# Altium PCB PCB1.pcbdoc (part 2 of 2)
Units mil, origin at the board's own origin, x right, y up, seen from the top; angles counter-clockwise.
Board outline 2817.44 x 1578.14 mil, 2 copper layers (Top Layer, Bottom Layer); 132 components, 113 nets, 538 pads, 285 vias.
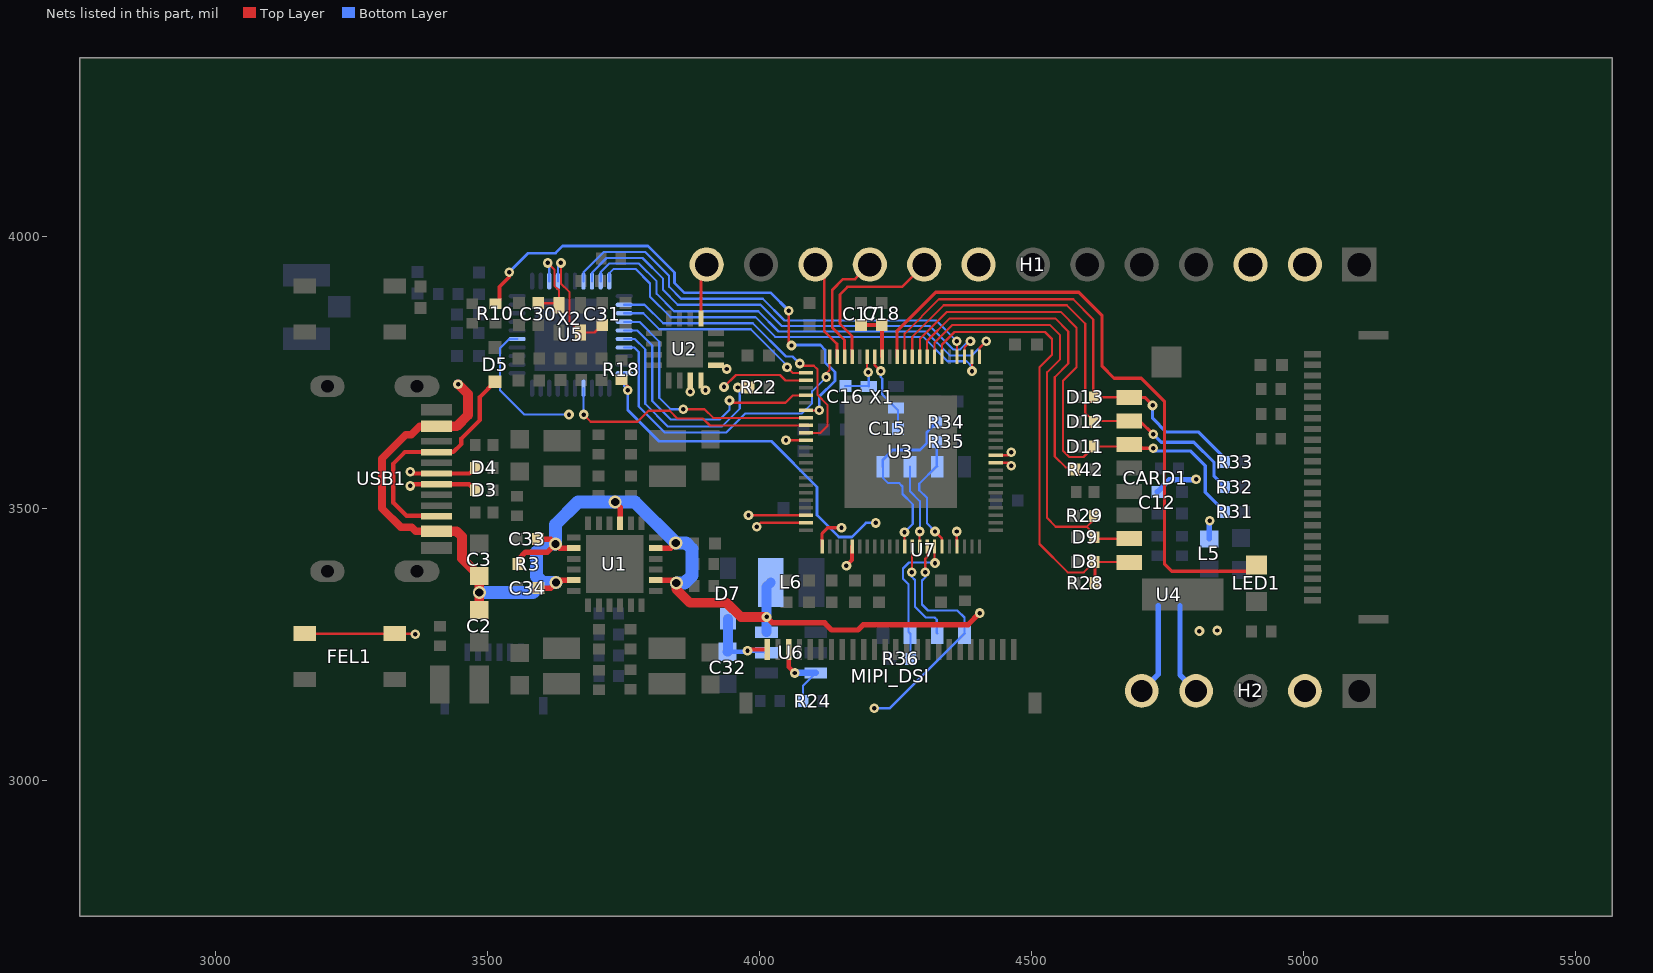
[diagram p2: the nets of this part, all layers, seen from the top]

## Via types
v1: diameter 18, hole 8, Top Layer to Bottom Layer, 271 vias
v2: diameter 24, hole 15, Top Layer to Bottom Layer, 14 vias

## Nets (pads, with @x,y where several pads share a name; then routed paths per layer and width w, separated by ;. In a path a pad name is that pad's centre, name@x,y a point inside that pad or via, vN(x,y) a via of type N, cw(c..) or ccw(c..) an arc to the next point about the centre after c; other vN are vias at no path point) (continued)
HX1: C30.1 U5.3 X2.1 | length 160.9
  Top Layer w4: C30.1@3592.85,3876.99 3626.85,3876.99 X2.1@3630.85,3872.99 3630.85,3900.78 3622.5,3909.13 3622.5,3939.13 v1(3610.5,3951.13)
  Bottom Layer w4: v1(3610.5,3951.13) 3613.13,3948.5 U5.3@3613.13,3917.53
HX2: C31.1 U5.4 X2.3 | length 224.6
  Top Layer w4: v1(3634.5,3951.13) 3634.5,3913.13 3650.5,3897.13 3650.5,3843.34 X2.3@3670.85,3822.99 3696.35,3822.99 C31.1@3710.5,3837.14
  Bottom Layer w4: U5.4@3628.88,3917.53 3628.88,3945.51 v1(3634.5,3951.13)
HXIN: C16.1 U3.16 X1.1 | length 99.2
  Top Layer w4: U3.16@4197.49,3778.64 4197.49,3752.14 v1(4199.5,3750.13)
  Bottom Layer w4: C16.1@4157.5,3725.05 4199.5,3725.05 X1.1@4200.5,3724.05 4200.5,3749.14 v1(4199.5,3750.13)
HXOUT: C15.1 U3.15 X1.3 | length 150.5
  Top Layer w4: U3.15@4211.27,3778.64 4211.27,3763.36 v1(4222.5,3752.13)
  Bottom Layer w4: v1(4222.5,3752.13) 4222.5,3741.13 4225.5,3738.13 4225.5,3709.05 X1.3@4250.5,3684.05 4254.49,3680.06 C15.1@4254.49,3646.05
LED: LED1.2 U3.12 | length 1184.7
  Top Layer w6: U3.12@4252.61,3778.64 4252.61,3826.24 4323.5,3897.13 4586.5,3897.13 4629.5,3854.13 4629.5,3761.13 4651.5,3739.13 4701.5,3739.13 4744.5,3696.13 4744.5,3397.13 4757.5,3384.13 4902.04,3384.13 LED1.2@4913.5,3395.6
LEDA: C32.2 D7.1 MIPI_DSI.24 U6.5 | length 172.8
  Top Layer w8: v1(3977.5,3238.13) 3979.7,3240.33 MIPI_DSI.24@4014.1,3240.33
  Bottom Layer w8: C32.2@3940.92,3236.06 3975.43,3236.06 v1(3977.5,3238.13) 4009.12,3238.13 U6.5@4012.72,3234.54
  Bottom Layer w18: C32.2@3940.92,3236.06 3941.5,3236.64 D7.1@3941.5,3296.93
LEDK: MIPI_DSI.22 R24.2 U6.3 | length 147.6
  Top Layer w8: MIPI_DSI.22@4053.5,3240.33 4053.5,3208.13 v1(4064.5,3197.13)
  Bottom Layer w4: R24.2@4079.92,3145.54 4079.92,3173.94 U6.3@4103.12,3197.14
  Bottom Layer w12: v1(4064.5,3197.13) U6.3@4103.12,3197.14
LINEOUTP: C12.1 U3.49 | length 1142.3
  Top Layer w7: v1(4159.5,3394.13) 4169.93,3404.56 U3.49@4169.93,3429.62
  Mid-Layer 1 w7: v1(4159.5,3394.13) 4302.5,3251.13 4456.5,3251.13 4491.5,3286.13 4796.5,3286.13 v1(4808.5,3274.13)
  Mid-Layer 2 w7: v1(4802.5,3553.13) 4807.5,3548.13 4807.5,3467.13 4823.5,3451.13 4823.5,3289.13 v1(4808.5,3274.13)
  Bottom Layer w10: C12.1@4731.05,3530.3 4752.88,3552.13 4798.5,3552.13 4799.5,3553.13 v1(4802.5,3553.13)
LPCLK: R18.1 U3.63 U5.20 | length 871.8
  Top Layer w4: R18.1@3745.67,3736.24 3757.5,3724.41 v1(3757.5,3717.13)
  Top Layer w5: v1(4362.5,3457.13) 4362.5,3429.97 U3.63@4362.85,3429.62
  Mid-Layer 1 w5: v1(4213.5,3473.13) 4346.5,3473.13 v1(4362.5,3457.13)
  Bottom Layer w4: U5.20@3750.9,3748.26 3750.9,3723.73 v1(3757.5,3717.13)
  Bottom Layer w5: v1(3757.5,3717.13) 3757.5,3680.13 3814.5,3623.13 4021.5,3623.13 4105.5,3539.13 4105.5,3487.21 4145.58,3447.13 4169.5,3447.13 4195.5,3473.13 v1(4213.5,3473.13)
PE10: H1.8 U3.32 | length 573
  Top Layer w5: v1(4048.5,3625.13) 4048.83,3624.8 U3.32@4084.99,3624.8
  Mid-Layer 2 w4: v1(4048.5,3625.13) 4087.5,3664.13 4087.5,3747.13 4144.5,3804.13 4187.5,3804.13 4289.5,3906.13 4360.5,3906.13 H1.8@4402.5,3948.13
PE11: H1.11 U3.20 | length 186
  Top Layer w5: H1.11@4102.5,3948.13 4118.5,3932.13 4118.5,3826.13 4142.37,3802.26 U3.20@4142.37,3778.64
PE12: H1.10 U3.19 | length 220.3
  Top Layer w5: U3.19@4156.15,3778.64 4156.15,3809.48 4133.5,3832.13 4133.5,3901.13 4153.5,3921.13 4175.5,3921.13 H1.10@4202.5,3948.13
PE13: H1.9 U3.18 | length 301.6
  Top Layer w5: U3.18@4169.93,3778.64 4169.93,3816.7 4147.5,3839.13 4147.5,3893.13 4161.5,3907.13 4261.5,3907.13 H1.9@4302.5,3948.13
PH0: H2.2 U3.45 | length 1113.8
  Top Layer w6: U3.45@4114.81,3429.62 4114.81,3453.68 4125.26,3464.13 v1(4150.5,3464.13)
  Mid-Layer 1 w6: v1(4150.5,3464.13) 4132.5,3446.13 4132.5,3398.13 4295.5,3235.13 4947.5,3235.13 5002.5,3180.13 H2.2@5002.5,3164.13
SDC0_CLK: R42.1 U3.8 | length 604
  Top Layer w4: U3.8@4307.73,3778.64 4307.73,3807.36 4349.5,3849.13 4543.5,3849.13 4567.5,3825.13 4567.5,3766.13 4542.5,3741.13 4542.5,3595.13 4562.5,3575.13 4576.51,3575.13 R42.1@4580.5,3571.14
SDC0_CMD: CARD1.3 D11.1 R31.1 U3.9 | length 982.1
  Top Layer w4: U3.9@4293.95,3778.64 4294.5,3779.19 4294.5,3811.13 4344.5,3861.13 4553.5,3861.13 4582.5,3832.13 4582.5,3759.13 4557.5,3734.13 4557.5,3606.13 4569.5,3594.13 4595.5,3594.13 4614.83,3613.47 D11.1@4615.24,3613.47 4675.63,3613.47 CARD1.3@4679.3,3617.13
  Top Layer w6: CARD1.3@4679.3,3617.13 4696.5,3617.13 4703.5,3610.13 v1(4723.5,3610.13)
  Bottom Layer w6: v1(4723.5,3610.13) 4728.5,3605.13 4792.5,3605.13 4819.5,3578.13 4819.5,3529.15 R31.1@4855.34,3493.31
SDC0_D0: CARD1.7 D9.1 R29.1 U3.7 | length 819.7
  Top Layer w4: U3.7@4321.51,3778.64 4321.51,3804.14 4354.5,3837.13 4533.5,3837.13 4552.5,3818.13 4552.5,3774.13 4528.5,3750.13 4528.5,3482.13 4544.5,3466.13 4601.5,3466.13 ; R29.1@4615.5,3486.13 4615.5,3480.13 4601.5,3466.13 ; CARD1.7@4679.3,3443.93 4618.04,3443.93 D9.1@4615.24,3446.73 4615.24,3452.39 4601.5,3466.13
SDC0_D1: CARD1.8 D8.1 R28.1 U3.6 | length 863.2
  Top Layer w4: U3.6@4335.29,3778.64 4335.29,3801.14 4358.29,3824.13 4524.5,3824.13 4537.5,3811.13 4537.5,3782.13 4514.5,3759.13 4514.5,3434.13 4566.5,3382.13 4596.02,3382.13 4613.78,3399.9 D8.1@4615.24,3401.36 ; D8.1@4611.72,3401.36 D8.1@4615.24,3401.36 ; CARD1.8@4679.3,3400.63 4678.58,3401.36 D8.1@4615.24,3401.36
  Top Layer w6: D8.1@4613.78,3399.9 4616.5,3397.18 R28.1@4616.5,3362.13
SDC0_D2: CARD1.1 D13.1 R33.1 U3.11 | length 882.7
  Top Layer w4: U3.11@4266.39,3778.64 4266.5,3778.75 4266.5,3821.13 4329.5,3884.13 4576.5,3884.13 4613.5,3847.13 4613.5,3705.95 D13.1@4615.24,3704.21 4678.83,3704.21 CARD1.1@4679.3,3703.73
  Top Layer w6: CARD1.1@4679.3,3703.73 4707.9,3703.73 v1(4722.5,3689.13)
  Bottom Layer w6: v1(4722.5,3689.13) 4722.5,3665.13 4747.5,3640.13 4807.5,3640.13 4855.34,3592.29 R33.1@4855.34,3584.68
SDC0_D3: CARD1.2 D12.1 R32.1 U3.10 | length 885.8
  Top Layer w4: U3.10@4280.17,3778.64 4280.5,3778.97 4280.5,3815.13 4338.5,3873.13 4564.5,3873.13 4598.5,3839.13 4598.5,3675.58 D12.1@4615.24,3658.84 4616.84,3660.43 CARD1.2@4679.3,3660.43
  Top Layer w6: CARD1.2@4679.3,3660.43 4699.2,3660.43 v1(4723.5,3636.13)
  Bottom Layer w6: v1(4723.5,3636.13) 4738.5,3621.13 4798.5,3621.13 4835.5,3584.13 4835.5,3558.83 R32.1@4855.34,3538.99
SDC1_CLK: R22.1 U5.16 | length 413.2
  Top Layer w4: v1(3959.5,3722.13) R22.1@3980.5,3722.14
  Bottom Layer w4: U5.16@3750.9,3811.26 3770.37,3811.26 3789.5,3792.13 3789.5,3692.13 3831.5,3650.13 3930.5,3650.13 3963.5,3683.13 3963.5,3718.13 v1(3959.5,3722.13)
SDC1_CMD: U3.31 U5.12 | length 561.1
  Top Layer w4: v1(4073.5,3766.13) 4077.5,3762.13 4099.5,3762.13 4106.5,3755.13 4106.5,3708.13 4124.5,3690.13 4124.5,3651.13 4111.95,3638.58 U3.31@4084.99,3638.58
  Bottom Layer w4: U5.12@3750.9,3874.25 3788.38,3874.25 3822.5,3840.13 3987.5,3840.13 4048.5,3779.13 4060.5,3779.13 v1(4073.5,3766.13)
SDC1_D0: U3.23 U5.13 | length 381.3
  Top Layer w4: v1(4050.5,3759.13) 4060.81,3748.82 U3.23@4084.99,3748.82
  Bottom Layer w4: U5.13@3750.9,3858.5 3786.13,3858.5 3815.5,3829.13 3983.5,3829.13 4050.5,3762.13 v1(4050.5,3759.13)
SDC1_D1: U3.29 U5.14 | length 467.6
  Top Layer w4: v1(3859.5,3682.13) 3898.5,3682.13 3914.49,3666.14 U3.29@4084.99,3666.14
  Bottom Layer w4: U5.14@3750.9,3842.75 3778.88,3842.75 3815.5,3806.13 3815.5,3703.13 3836.5,3682.13 v1(3859.5,3682.13)
SDC1_D2: U3.21 U5.17 | length 590.1
  Top Layer w4: v1(4122.5,3741.13) 4122.5,3748.13 4128.59,3754.22 U3.21@4128.59,3778.64
  Bottom Layer w4: U5.17@3750.9,3795.51 3769.12,3795.51 3777.5,3787.13 3777.5,3687.13 3825.5,3639.13 3938.5,3639.13 3973.5,3674.13 4077.5,3674.13 4096.5,3693.13 4096.5,3715.13 v1(4122.5,3741.13)
SDC1_D3: U3.26 U5.15 | length 493.4
  Top Layer w4: v1(3944.5,3698.13) 3948.5,3694.13 4047.5,3694.13 4060.85,3707.48 U3.26@4084.99,3707.48
  Bottom Layer w4: U5.15@3750.9,3827 3774.63,3827 3802.5,3799.13 3802.5,3697.13 3836.5,3663.13 3926.5,3663.13 3944.5,3681.13 v1(3944.5,3698.13)
SPI0_CLK: U3.57 U7.6 | length 189.1
  Top Layer w4: v1(4279.5,3382.13) 4280.17,3382.8 U3.57@4280.17,3429.62
  Bottom Layer w4: v1(4279.5,3382.13) 4279.5,3374.13 4285.5,3368.13 4285.5,3319.13 4305.5,3299.13 4321.5,3299.13 4325.5,3295.13 4325.5,3270.63 U7.6@4326.5,3269.63
SPI0_CS: R34.1 U3.56 U7.1 | length 339.8
  Top Layer w4: U3.56@4266.39,3429.62 4266.5,3456.13 v1(4266.39,3456.02)
  Bottom Layer w4: U7.1@4226.5,3576.63 4226.5,3556.13 4236.5,3546.13 4256.5,3546.13 4262.5,3540.13 4262.5,3526.13 4281.5,3507.13 4281.5,3471.13 v1(4266.39,3456.02)
  Bottom Layer w5: U7.1@4226.5,3576.63 4226.5,3589.13 4244.5,3607.13 4294.5,3607.13 4307.5,3620.13 4307.5,3640.12 R34.1@4325.5,3658.13
SPI0_HOLD: R36.1 U3.60 U7.7 | length 266.7
  Top Layer w4: U3.60@4321.51,3429.62 4321.51,3400.12 v1(4322.5,3399.13)
  Bottom Layer w4: R36.1@4277.5,3223.14 4277.5,3268.63 U7.7@4276.5,3269.63 4273.5,3272.63 4273.5,3360.13 4263.5,3370.13 4263.5,3389.13 4274.5,3400.13 4321.5,3400.13 v1(4322.5,3399.13)
SPI0_MISO: U3.58 U7.2 | length 154.7
  Top Layer w4: U3.58@4293.95,3429.62 4293.95,3456.58 v1(4294.5,3457.13)
  Bottom Layer w4: U7.2@4276.5,3576.63 4276.5,3531.13 4294.5,3513.13 v1(4294.5,3457.13)
SPI0_MOSI: FEL1.1 FEL1.2 U3.59 U7.5 | length 1587.1
  Top Layer w4: v1(4304.5,3382.13) 4304.5,3407.13 4307.73,3410.36 U3.59@4307.73,3429.62
  Top Layer w5: FEL1.1@3165.8,3269.43 3331.2,3269.43 3365.2,3269.43 v1(3366.5,3268.13)
  Mid-Layer 1 w6: v1(3366.5,3268.13) 3382.5,3284.13 3410.5,3284.13 3436.5,3310.13 3623.5,3310.13 3756.5,3177.13 3799.5,3177.13 3844.5,3132.13 v1(4210.5,3132.13)
  Bottom Layer w4: v1(4304.5,3382.13) 4304.5,3373.13 4298.5,3367.13 4298.5,3323.13 4309.5,3312.13 4363.5,3312.13 4376.5,3299.13 U7.5@4376.5,3269.63
  Bottom Layer w5: v1(4210.5,3132.13) 4239,3132.13 U7.5@4376.5,3269.63
SPI0_WP: R35.1 U3.61 U7.3 | length 224.8
  Top Layer w4: v1(4322.5,3457.13) 4335.28,3444.35 U3.61@4335.28,3429.62
  Bottom Layer w4: v1(4322.5,3457.13) 4307.5,3472.13 4307.5,3519.13 4293.5,3533.13 4293.5,3545.13 4325,3576.63 U7.3@4326.5,3576.63 4325.5,3577.63 R35.1@4325.5,3622.13
SPK+: H2.4 U4.C3 | length 169
  Bottom Layer w10: U4.C3@4772.85,3320.88 4772.85,3193.78 H2.4@4802.5,3164.13
SPK-: H2.5 U4.A3 | length 169.3
  Bottom Layer w10: H2.5@4702.5,3164.13 4732.85,3194.49 U4.A3@4732.85,3320.88
UART0_RX: H1.3 U2.4 U3.42 | length 1842.1
  Top Layer w4: U2.4@3892.09,3735.04 3892.09,3725.55 v1(3900.5,3717.13) ; v1(3979.5,3487.13) 3979.63,3487 U3.42@4084.99,3487
  Mid-Layer 1 w5: v1(3900.5,3717.13) 3923.5,3740.13 3954.5,3740.13 3955.5,3741.13 4023.5,3741.13 4081.28,3683.35 4081.28,3512.91 4055.5,3487.13 v1(3979.5,3487.13)
  Mid-Layer 2 w4: v1(3979.5,3487.13) 3987.5,3495.13 4161.5,3495.13 4294.5,3628.13 4294.5,3805.13 4329.5,3840.13 4794.5,3840.13 H1.3@4902.5,3948.13
UART0_TX: H1.2 U2.5 U3.43 | length 1905.5
  Top Layer w4: U2.5@3919.59,3762.61 3933.02,3762.61 v1(3939.5,3756.13) ; v1(3994.5,3466.13) 4001.59,3473.22 U3.43@4084.99,3473.22
  Mid-Layer 1 w5: v1(3939.5,3756.13) 3943.5,3752.13 4029.5,3752.13 4092.28,3689.35 4092.28,3506.91 4059.5,3474.13 4002.5,3474.13 v1(3994.5,3466.13)
  Mid-Layer 2 w4: v1(3994.5,3466.13) 4009.5,3481.13 4168.5,3481.13 4307.5,3620.13 4307.5,3798.13 4334.5,3825.13 4879.5,3825.13 H1.2@5002.5,3948.13
UART2_CTS: U3.4 U5.7 | length 826.4
  Top Layer w4: v1(4362.5,3807.13) 4362.85,3806.78 U3.4@4362.85,3778.64
  Bottom Layer w4: U5.7@3676.12,3917.53 3676.12,3933.75 3713.5,3971.13 3789.5,3971.13 3833.5,3927.13 3833.5,3907.13 3855.5,3885.13 4005.5,3885.13 4045.5,3845.13 4324.5,3845.13 v1(4362.5,3807.13)
UART2_RTS: U3.3 U5.8 | length 843.7
  Top Layer w4: U3.3@4376.63,3778.64 4376.63,3796.26 v1(4387.5,3807.13)
  Bottom Layer w4: U5.8@3691.87,3917.53 3691.87,3933.5 3718.5,3960.13 3784.5,3960.13 3822.5,3922.13 3822.5,3901.13 3849.5,3874.13 4001.5,3874.13 4040.5,3835.13 4312.5,3835.13 4355.5,3792.13 4368.71,3792.13 4383.71,3807.13 v1(4387.5,3807.13)
UART2_RX: U3.2 U5.10 | length 808.1
  Top Layer w4: U3.2@4390.41,3778.64 4390.41,3752.22 v1(4390.5,3752.13)
  Bottom Layer w4: U5.10@3723.37,3917.53 3723.37,3932 3731.5,3940.13 3771.5,3940.13 3798.5,3913.13 3798.5,3889.13 3836.5,3851.13 3992.5,3851.13 4028.5,3815.13 4300.5,3815.13 4345.5,3770.13 4380.5,3770.13 4390.5,3760.13 v1(4390.5,3752.13)
UART2_TX: U3.1 U5.9 | length 860.2
  Top Layer w4: U3.1@4404.19,3778.64 4404.19,3794.82 v1(4416.5,3807.13)
  Bottom Layer w4: U5.9@3707.62,3917.53 3707.62,3934.25 3723.5,3950.13 3777.83,3950.13 3810.5,3917.46 3810.5,3894.13 3842.5,3862.13 3997.5,3862.13 4034.5,3825.13 4305.5,3825.13 4349.5,3781.13 4390.5,3781.13 v1(4416.5,3807.13)
USB0_ID: D5.2 USB1.A5 USB1.B5 | length 441.7
  Top Layer w8: USB1.B5@3405.8,3485.23 3404.9,3486.13 3350.5,3486.13 3326.5,3510.13 3326.5,3582.13 3347.7,3603.33 USB1.A5@3405.8,3603.33 3436.7,3603.33 3451.5,3618.13 3451.5,3628.13 3485.5,3662.13 3485.5,3704.63 D5.2@3513.5,3732.63
USB_D+: D4.1 U3.76 USB1.A6 | length 1674
  Top Layer w5: U3.76@4434.01,3583.46 4457.17,3583.46 v1(4462.5,3578.13)
  Top Layer w8: v1(3357.5,3567.13) 3360.7,3563.93 USB1.A6@3405.8,3563.93 3466.9,3563.93 D4.1@3477.1,3574.13
  Mid-Layer 1 w5: v1(3357.5,3567.13) 3341,3567.13 3333.5,3559.63 3325.61,3559.63 3309.97,3575.27 3309.97,3593.52 3326.59,3610.13 3447.17,3610.13 3534.5,3697.47 3534.5,3760.13 3569.34,3794.97 3794.34,3794.97 3833.5,3834.13 4195.5,3834.13 4363.23,3666.4 4363.23,3597.9 4385.28,3575.86 4416.38,3575.86 4425.66,3585.13 4439,3585.13 4446,3578.13 v1(4462.5,3578.13)
USB_D-: D3.1 U3.77 USB1.A7 | length 1713.6
  Top Layer w5: U3.77@4434.01,3597.24 4456.61,3597.24 v1(4462.5,3603.13)
  Top Layer w8: v1(3357.5,3541.13) 3360.7,3544.33 USB1.A7@3405.8,3544.33 3465.9,3544.33 D3.1@3477.1,3533.13
  Mid-Layer 1 w5: v1(3357.5,3541.13) 3341,3541.13 3333.5,3548.63 3318.11,3548.63 3298.97,3567.77 3298.97,3598.07 3322.03,3621.13 3442.61,3621.13 3523.5,3702.02 3523.5,3766.13 3563.34,3805.97 3790.34,3805.97 3829.5,3845.13 4200.06,3845.13 4374.23,3670.96 4374.23,3602.46 4389.83,3586.86 4411.83,3586.86 4421.1,3596.13 4439,3596.13 4446,3603.13 v1(4462.5,3603.13)
USB_ID: R10.1 U3.28 | length 950.4
  Top Layer w4: U3.28@4084.99,3679.92 4109.29,3679.92 v1(4109.5,3680.13)
  Top Layer w5: v1(4053.5,3863.13) 4053.5,3804.13 v1(4058.5,3799.13)
  Top Layer w7: R10.1@3513.83,3875.92 3521.5,3883.59 3521.5,3907.13 3539.5,3925.13 v1(3539.5,3934.13)
  Bottom Layer w5: v1(3539.5,3934.13) 3574.5,3969.13 3624.5,3969.13 3637.5,3982.13 3794.5,3982.13 3843.5,3933.13 3843.5,3914.13 3861.5,3896.13 4020.5,3896.13 v1(4053.5,3863.13) ; v1(4058.5,3799.13) 4059.5,3800.13 4111.5,3800.13 4120.5,3791.13 4120.5,3768.13 4138.5,3750.13 4138.5,3734.13 4109.5,3705.13 v1(4109.5,3680.13)
VBUS: C2.2 C3.2 C33.1 C34.1 H1.13 L5.1 L6.1 R3.2 U1.3 U1.8 U1.11 U1.20 U1.23 U2.3 U2.9 U6.6 USB1.A4B9 USB1.B4A9 | length 4231.5
  Top Layer w4: U2.3@3872.41,3735.05 3872.41,3714.23 v1(3872.5,3714.13)
  Top Layer w6: U2.9@3892.03,3849.22 3892.03,3937.66 H1.13@3902.5,3948.13
  Top Layer w10: R3.2@3555.67,3397.25 3555.67,3405.25 3569.67,3419.26 3609.67,3419.26 v2(3624.67,3434.26) ; C33.1@3592.67,3443.26 3615.67,3443.26 v2(3624.67,3434.26) ; C34.1@3593.67,3353.26 3615.67,3353.26 v2(3625.67,3363.26) 3630.14,3367.72 U1.11@3658.41,3367.72 ; U1.8@3658.41,3426.78 3632.14,3426.78 v2(3624.67,3434.26) ; v2(3734.32,3511.18) 3743.51,3501.99 U1.3@3743.51,3472.51 ; U1.20@3808.93,3367.72 3841.2,3367.72 v2(3846.67,3362.26) ; U1.23@3808.93,3426.78 3836.2,3426.78 v2(3845.67,3436.26) ; v1(4012.72,3300.2) 4023.79,3289.13 4119.5,3289.13 4132.5,3276.13 4180.5,3276.13 4190.5,3286.13 4383.5,3286.13 v1(4404.5,3307.13)
  Top Layer w14: USB1.B4A9@3405.8,3457.63 3368,3457.63 3360.5,3465.13 3340.5,3465.13 3305.5,3500.13 3305.5,3591.13 3349.5,3635.13 3359.5,3635.13 3375,3650.63 USB1.A4B9@3405.8,3650.63
  Top Layer w18: USB1.B4A9@3405.8,3457.63 3443,3457.63 3452.5,3448.13 3452.5,3407.6 C3.2@3484.5,3375.6 v2(3484.5,3344.85) C2.2@3484.5,3312.66 ; USB1.A4B9@3405.8,3650.63 3443,3650.63 3463.5,3671.13 3463.5,3710.13 v1(3445.5,3728.13) ; v2(3846.67,3362.26) 3846.67,3350.96 3871.5,3326.13 3939.5,3326.13 3965.43,3300.2 v1(4012.72,3300.2)
  Mid-Layer 1 w10: v2(3734.32,3511.18) 3733.5,3512 3733.5,3655.13 3805.5,3727.13 3859.5,3727.13 v1(3872.5,3714.13) ; v1(4404.5,3307.13) 4407.5,3304.13 4812.5,3304.13 v1(4841.5,3275.13)
  Mid-Layer 1 w18: v1(3445.5,3728.13) 3445.5,3926.13 3505.5,3986.13 3864.5,3986.13 H1.13@3902.5,3948.13
  Mid-Layer 2 w10: v1(4827.5,3477.13) 4841.5,3463.13 v1(4841.5,3275.13)
  Bottom Layer w10: L5.1@4826.85,3443.43 4826.85,3476.48 v1(4827.5,3477.13)
  Bottom Layer w18: U6.6@4012.72,3271.94 v1(4012.72,3300.2) 4012.72,3355.74 L6.1@4020.52,3363.54
  Bottom Layer w24: v2(3484.5,3344.85) 3582.98,3344.85 3601.38,3363.26 ; v2(3625.67,3363.26) 3601.38,3363.26 ; v2(3846.67,3362.26) 3861.62,3362.26 3875.5,3376.13 3875.5,3425.13 3864.38,3436.26 v2(3845.67,3436.26) 3770.75,3511.18 v2(3734.32,3511.18) 3665.55,3511.18 3624.5,3470.13 3624.5,3434.43 v2(3624.67,3434.26) 3624.55,3434.13 3604.5,3434.13 3589.67,3419.3 3589.67,3374.96 3601.38,3363.26
VCC_LDOA: C17.2 C18.2 U3.14 | length 97
  Top Layer w7: C17.2@4186.3,3837.05 C18.2@4224.15,3837.05 ; C18.2@4224.43,3837.33 C18.2@4224.15,3837.05 ; U3.14@4225.05,3778.64 4225.05,3836.15 C18.2@4224.15,3837.05
WL_REG_ON: U3.30 U5.24 | length 482.2
  Top Layer w4: v1(3676.5,3672.13) 3689.5,3659.13 3775.5,3659.13 3795.5,3679.13 3834.5,3679.13 3848.5,3665.13 3895.5,3665.13 3908.5,3652.13 4084.76,3652.13 U3.30@4084.99,3652.36
  Bottom Layer w4: U5.24@3676.12,3720.73 3676.12,3672.51 v1(3676.5,3672.13)
WL_WAKE_AP: U3.24 U5.35 | length 745.3
  Top Layer w4: v1(3934.5,3723.13) 3956.5,3745.13 4037.5,3745.13 4047.59,3735.04 U3.24@4084.99,3735.04
  Mid-Layer 2 w4: v1(3649.5,3672.13) 3666.5,3655.13 3751.5,3655.13 3786.5,3690.13 3842.5,3690.13 3851.5,3699.13 3910.5,3699.13 v1(3934.5,3723.13)
  Bottom Layer w4: U5.35@3554.1,3811.26 3539.63,3811.26 3522.5,3794.13 3522.5,3717.13 3567.5,3672.13 v1(3649.5,3672.13)
"": 
pads on no net: FPC1.1 FPC1.2 FPC1.20 FPC1.21 FPC1.22 FPC1.23 FPC1.24 MIPI_DSI.16 MIPI_DSI.20 MIPI_DSI.21 U1.15 U1.16 U2.10 U2.11 U2.12 U2.13 U2.14 U2.15 U2.16 U3.46 U3.52 U3.53 U3.65 U5.18 U5.27 U5.29 U5.31 U5.32 U5.33 U5.34 U5.39 USB1.A8 USB1.B8

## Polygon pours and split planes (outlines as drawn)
GND on Mid-Layer 1 (solid, remove dead copper, pour order 1): 3006.49,3016.56 5251.49,3016.56 5251.49,4072.56 3006.49,4072.56
3V3 on Mid-Layer 2 (solid, remove dead copper, pour order 2): 3015,3008.13 5260,3008.13 5260,4064.13 3015,4064.13
GND on Bottom Layer (solid, remove dead copper, pour order 3): 3023,3000 5268,3000 5268,4056 3023,4056
GND on Top Layer (solid, remove dead copper, pour order 4): 3000,3022.14 5245,3022.14 5245,4078.14 3000,4078.14
3V3 on Mid-Layer 1 (solid, remove dead copper): 3681,3240.63 3681,3140.63 3658.5,3118.13 3293.5,3118.13 3254.5,3157.13 3254.5,3222.13 3342.5,3310.13 3611.5,3310.13

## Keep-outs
Mid-Layer 1:
  region: 4396.5,3556.13 4396.5,3509.26 4495.71,3410.05 5039.97,3410.05 5104.06,3474.13 5104.06,3522.57 5027.5,3599.13 4728.47,3599.13 4711.71,3582.37 4422.74,3582.37
Bottom Layer:
  region: 3100.5,3788.57 3246.5,3788.57 3246.5,3949.17 3100.5,3949.17
  region: 4400.5,3642.13 4438.5,3642.13 4448.5,3632.13 4448.5,3618.13 4551.5,3515.13 4551.5,3352.81 4483.69,3288.04 4407.77,3288.7 4321.4,3202.33 4321.4,3157.23 4351.5,3127.13 4513.5,3127.13 4664.5,3278.13 4664.5,3579.13 4519.5,3724.13 4413.5,3724.13 4392.5,3703.13 4392.5,3650.13

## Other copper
Top Layer:
  drawing of 418 lines, arcs and shapes, not listed
  text "Lizard" at 3142.82,3649.59 h38.94 r270
Mid-Layer 1:
  region net VBUS: 3904.47,3979.57 3871,3992.36 3858.27,3979.63 3871.06,3946.16
  region net PH0: 5015.6,3192.23 4976.56,3210.31 4970.66,3207.73 4972.99,3173.62
  region net VBUS: 3742.76,3519.71 3738.5,3531.91 3728.5,3531.23 3724.8,3518.49
  region net $1N18373: 3615.23,3406.23 3607.38,3411.61 3600.31,3404.54 3605.69,3396.69
  region net 3V3: 3667.25,3699.09 3665.5,3705.13 3655.5,3705.13 3653.75,3699.09
  region net 3V3: 3590.48,3691.57 3595.85,3699.42 3588.78,3706.49 3580.94,3701.12
  region net USB_D+: 3351.55,3573.88 3342.2,3569.63 3342.2,3564.63 3351.55,3560.38
  region net USB_D-: 3351.55,3547.88 3342.2,3543.63 3342.2,3538.63 3351.55,3534.38
  region net VBUS: 3873.06,3723.12 3865.22,3728.49 3858.15,3721.42 3863.52,3713.57
  region net UART0_RX: 3909.48,3716.57 3913.09,3726.18 3909.55,3729.72 3899.94,3726.12
  region net UART0_TX: 3941.83,3747.44 3953.35,3749.63 3955.84,3754.63 3947.83,3759.53
  region net UART0_RX: 3985.45,3480.38 3994.8,3484.63 3994.8,3489.63 3985.45,3493.88
  region net UART0_TX: 4003.48,3465.57 4004.27,3472.37 4000.73,3475.9 3993.94,3475.12
  region net LPCLK: 4363.06,3466.12 4353.45,3469.72 4349.91,3466.18 4353.52,3456.57
  region net USB_D-: 4456.55,3609.88 4447.2,3605.63 4447.2,3600.63 4456.55,3596.38
  region net USB_D+: 4456.55,3584.88 4447.2,3580.63 4447.2,3575.63 4456.55,3571.38
  region net LINEOUTP: 4158.94,3385.15 4167.84,3380.84 4172.79,3385.79 4168.48,3394.7
  region net CSI_CKP: 4487.44,3553.13 4500.42,3553.63 4504.9,3558.63 4496.44,3563.2
  region net CSI_CKN: 4496.44,3538.07 4504.9,3542.63 4500.42,3547.63 4487.44,3548.13
  region net CSI_CKP: 4960.8,3588.44 4952.77,3583.63 4956.11,3578.63 4968.3,3577.21
  region net CSI_CKN: 4969.56,3573.13 4956.58,3572.63 4952.1,3567.63 4960.56,3563.07
  region net CSI_CKN: 4969.56,3573.13 4956.58,3572.63 4952.1,3567.63 4960.56,3563.07
  region net CSI_D1N: 4404.94,3527.15 4413.73,3524.37 4417.27,3527.9 4414.48,3536.7
  region net CSI_D1P: 4414.44,3509.07 4422.9,3513.63 4418.42,3518.63 4405.44,3519.13
  region net CSI_D1N: 5058.48,3449.57 5058.27,3455.37 5054.73,3458.9 5048.94,3459.12
  region net CSI_D1P: 5049.44,3465.13 5062.42,3465.63 5066.9,3470.63 5058.44,3475.2
  region net CSI_D0P: 4490.58,3483.93 4492,3471.74 4497,3468.4 4501.81,3476.43
  region net CSI_D0N: 4474.64,3476.13 4481.73,3475.37 4485.27,3478.9 4483.41,3486.4
  region net CSI_D0P: 4925.44,3489.2 4930,3480.74 4935,3485.21 4935.5,3498.2
  region net CSI_D0N: 4943.52,3497.7 4941.73,3489.9 4945.27,3486.37 4953.06,3488.15
  region net CSI_MCLK: 5047.52,3341.7 5043.91,3332.08 5047.45,3328.55 5057.06,3332.15
  region net CSI_SDA: 5086.52,3417.7 5082.91,3408.08 5086.45,3404.55 5096.06,3408.15
  region net CSI_SCK: 5118.06,3435.12 5108.45,3438.72 5104.91,3435.18 5108.52,3425.57
  region net CSI_SDA: 4474.94,3405.15 4483.73,3402.37 4487.27,3405.9 4484.48,3414.7
  region net CSI_SCK: 4499.94,3417.15 4509.55,3413.55 4513.09,3417.08 4509.48,3426.7
  region net CSI_MCLK: 4403.94,3327.15 4413.55,3323.55 4417.09,3327.08 4413.48,3336.7
  region net CSI_RSTN: 4447.83,3365.44 4459.35,3367.63 4461.84,3372.63 4453.83,3377.53
  region net CSI_RSTN: 5128.5,3400.99 5125.28,3391.45 5129.09,3388.19 5138.77,3392.22
  region net VBUS: 4407.86,3298.78 4417.9,3299.13 4421.44,3309.13 4412.36,3311.51
  region net VBUS: 4842.06,3284.12 4834.22,3289.49 4827.15,3282.42 4832.52,3274.57
  region net LPCLK: 4219.45,3466.38 4228.8,3470.63 4228.8,3475.63 4219.45,3479.88
  region net SPI0_MOSI: 4204.55,3138.88 4195.2,3135.13 4195.2,3129.13 4204.55,3125.38
  region net SPI0_MOSI: 3375.48,3267.57 3379.44,3276.83 3375.2,3281.07 3365.94,3277.12
  region net LINEOUTP: 4809.06,3283.12 4800.16,3287.43 4795.21,3282.48 4799.52,3273.57
  region net 3V3: 3667.25,3699.09 3665.5,3705.13 3655.5,3705.13 3653.75,3699.09
  region net PH0: 4141.52,3464.7 4137.56,3455.44 4141.8,3451.19 4151.06,3455.15
  region net $1N18373: 3577.75,3472.18 3579.5,3462.83 3589.5,3462.83 3591.25,3472.18
Mid-Layer 2:
  region net UART0_TX: 4971.06,3950.11 4963.22,3911.68 4966.05,3908.85 5004.47,3916.69
  region net UART0_RX: 4871.06,3950.11 4863.22,3911.68 4866.05,3908.85 4904.47,3916.69
  region net CTP_SCL: 4771.06,3950.11 4763.22,3911.68 4766.05,3908.85 4804.47,3916.69
  region net CTP_SDA: 4671.06,3950.11 4663.22,3911.68 4666.05,3908.85 4704.47,3916.69
  region net CTP_EINT: 4571.06,3950.11 4563.22,3911.68 4566.05,3908.85 4604.47,3916.69
  region net CTP_RST: 4471.06,3950.11 4463.22,3911.68 4466.05,3908.85 4504.47,3916.69
  region net PE10: 4371.06,3950.11 4363.22,3911.68 4366.05,3908.85 4404.47,3916.69
  region net $3N3727: 3621.5,3692.28 3625.86,3700.84 3619.76,3706.05 3611.23,3701.04
  region net $3N3727: 3708.18,3701.24 3699.63,3705.9 3693.97,3700.24 3698.64,3691.69
  region net DU0+: 3459.88,3508.17 3463.13,3518.14 3460.3,3520.97 3450.33,3517.72
  region net DU0-: 3464.31,3592.64 3463.5,3606.27 3459.5,3610.05 3454.5,3601.91
  region net DU0-: 3464.31,3592.64 3463.5,3606.27 3459.5,3610.05 3454.5,3601.91
  region net WL_WAKE_AP: 3925.52,3723.7 3922.27,3713.73 3925.1,3710.9 3935.06,3714.15
  region net WL_WAKE_AP: 3648.94,3663.15 3658.9,3659.9 3661.73,3662.73 3658.48,3672.7
  region net DU0-: 3973.65,3819.09 3963.89,3821.57 3961.52,3818.29 3965.72,3808.16
  region net DU0+: 3946.55,3812.88 3937.2,3808.13 3937.2,3804.13 3946.55,3799.38
  region net UART0_RX: 3988.48,3486.57 3988.91,3493.72 3986.09,3496.55 3978.94,3496.12
  region net UART0_TX: 4003.48,3465.57 4006.73,3475.54 4003.9,3478.37 3993.94,3475.12
  region net GND: 4013.25,3774.09 4011.5,3783.43 4001.5,3783.43 3999.75,3774.09
  region net PE10: 4057.48,3624.57 4060.73,3634.54 4057.9,3637.37 4047.94,3634.12
  region net GND: 3885.45,3804.38 3894.8,3806.13 3894.8,3816.13 3885.45,3817.88
  region net VBUS: 4848.25,3281.09 4846.5,3290.43 4836.5,3290.43 4834.75,3281.09
  region net VBUS: 4826.94,3468.15 4834.78,3462.78 4841.85,3469.85 4836.48,3477.7
  region net LINEOUTP: 4800.19,3544.43 4804,3535.73 4811,3540.41 4811.42,3551.93
  region net CTP_SCL: 3945.75,3484.18 3950.5,3474.83 3954.5,3474.83 3959.25,3484.18
  region net CTP_SCL: 3961.48,3489.57 3964.73,3499.54 3961.9,3502.37 3951.94,3499.12
  region net CTP_SDA: 3942.52,3520.7 3939.27,3510.73 3942.1,3507.9 3952.06,3511.15
  region net CTP_SDA: 3958.8,3514.87 3967.19,3520.13 3966.28,3524.13 3955.8,3528.04
  region net CTP_EINT: 3975.45,3533.38 3984.8,3538.13 3984.8,3542.13 3975.45,3546.88
  region net CTP_EINT: 3963.55,3546.88 3954.2,3542.13 3954.2,3538.13 3963.55,3533.38
  region net CTP_RST: 3980.55,3565.88 3971.2,3561.13 3971.2,3557.13 3980.55,3552.38
  region net CTP_RST: 3992.45,3552.38 4001.8,3557.13 4001.8,3561.13 3992.45,3565.88
  region net LINEOUTP: 4817.48,3273.57 4821.79,3282.48 4816.84,3287.43 4807.94,3283.12
  region net CTP_RST: 3371.94,3223.15 3381.9,3219.9 3384.73,3222.73 3381.48,3232.7
  region net CTP_SDA: 3381.98,3184.14 3379.91,3189.72 3377.09,3192.55 3369.45,3189.17
  region net CTP_SCL: 3453.25,3173.09 3448.5,3182.43 3444.5,3182.43 3439.75,3173.09
  region net CTP_EINT: 3513.56,3151.2 3505.55,3146.13 3509.13,3142.13 3522.56,3141.13
  region net CTP_EINT: 3513.56,3151.2 3505.55,3146.13 3509.13,3142.13 3522.56,3141.13
Bottom Layer:
  region net $3N3729: 3276.19,3873.95 3276.28,3894.45 3247.18,3889.82 3247.18,3850.45
  region net $3N3729: 3370.64,3884.48 3399.4,3882.8 3399.4,3904.8 3370.64,3904.48
  region net $3N3728: 3483.33,3903.8 3455.09,3904.8 3455.09,3882.8 3483.33,3883.8
  region net $3N3728: 3445.25,3903.8 3445.25,3883.8 3472.64,3882.48 3472.64,3904.48
  region net $3N3728: 3523.84,3882.15 3524.61,3902.15 3494.64,3904.48 3494.64,3882.48
  region net $3N3729: 3329.7,3882.52 3359.64,3883.48 3359.64,3905.48 3329.7,3902.61
  region net $3N3729: 3408.56,3884.48 3408.56,3904.48 3381.64,3905.48 3381.64,3883.48
  region net 3V3: 4718.5,3576.13 4718.5,3570.13 4727.16,3562.63 4727.16,3583.63
  region net $2N11171: 4735.92,3363.59 4735.85,3367.84 4729.85,3367.84 4729.78,3363.59
  region net $2N10833: 4776.94,3360.62 4778.48,3362.26 4774.24,3366.5 4772.6,3364.96
  region net $2N10833: 4779.36,3393.62 4786.86,3402.62 4765.86,3402.62 4773.36,3393.62
  region net $2N10977: 4779.36,3467.31 4773.36,3467.31 4765.86,3458.31 4786.86,3458.31
  region net $2N10977: 4779.36,3470.3 4786.86,3479.3 4765.86,3479.3 4773.36,3470.3
  region net $2N11171: 4735.85,3393.62 4742.04,3402.62 4722.35,3402.62 4729.85,3393.62
  region net $2N11292: 4728.04,3467.31 4720.54,3458.31 4741.54,3458.31 4734.04,3467.31
  region net LINEOUTP: 4745.58,3551.91 4720.05,3541.3 4742.05,3519.3 4752.65,3544.84
  region net $2N11292: 4728.04,3470.3 4734.04,3470.3 4741.54,3479.3 4720.54,3479.3
  region net $2N11927: 4823.5,3362.13 4831.5,3362.13 4841.5,3372.57 4813.5,3372.57
  region net $2N11927: 4852.86,3391.32 4843.86,3398.82 4843.86,3377.82 4852.86,3385.32
  region net VBUS: 4831.85,3474.18 4821.85,3474.18 4809.84,3459.18 4843.86,3459.18
  region net $2N11927: 4859.12,3391.32 4859.12,3385.32 4868.12,3377.82 4868.12,3398.82
  region net HXIN: 4174.5,3723.05 4174.5,3727.05 4168.5,3732.05 4168.5,3718.05
  region net HXOUT: 4252.49,3663.05 4247.49,3657.05 4261.49,3657.05 4256.49,3663.05
  region net HXIN: 4179.5,3723.05 4185.5,3718.05 4185.5,3732.05 4179.5,3727.05
  region net HXIN: 4202.5,3740.05 4198.5,3740.05 4193.5,3734.05 4207.5,3734.05
  region net HXOUT: 4233.43,3698.3 4235.5,3689.15 4250.4,3694.05 4239.08,3698.3
  region net HXOUT: 4252.49,3668.05 4256.49,3668.05 4261.49,3674.05 4247.49,3674.05
  region net $3N3727: 3565.69,3913.53 3578.36,3903.53 3578.36,3931.53 3565.69,3921.53
  region net HX1: 3615.13,3938.74 3611.13,3938.74 3609.19,3929.34 3617.07,3929.34
  region net HX2: 3630.88,3938.74 3626.88,3938.74 3624.94,3929.34 3632.82,3929.34
  region net AP_WAKE_BT: 3642.63,3938.26 3640.69,3929.34 3648.57,3929.34 3646.63,3938.26
  region net BT_WAKE_AP: 3658.37,3937 3656.43,3929.34 3664.31,3929.34 3662.37,3937
  region net UART2_CTS: 3674.12,3933.75 3672.18,3929.34 3680.06,3929.34 3678.12,3933.75
  region net UART2_RTS: 3689.87,3933.5 3687.93,3929.34 3695.81,3929.34 3693.87,3933.5
  region net UART2_TX: 3705.62,3934.25 3703.68,3929.34 3711.56,3929.34 3709.62,3934.25
  region net $3N3721: 3731.55,3707.91 3727.31,3732.54 3720.75,3705.98 3731.05,3702.76
  region net BT_RSTN: 3689.87,3699.53 3693.87,3699.53 3695.81,3708.92 3687.93,3708.92
  region net WL_REG_ON: 3674.12,3699.53 3678.12,3699.53 3680.06,3708.92 3672.18,3708.92
  region net LPCLK: 3748.9,3738.33 3752.9,3738.33 3757.9,3744.33 3743.9,3744.33
  region net SDC1_D2: 3769.12,3797.51 3762.71,3799.45 3762.71,3791.58 3769.12,3793.51
  region net SDC1_CLK: 3770.37,3813.26 3762.71,3815.2 3762.71,3807.33 3770.37,3809.26
  region net SDC1_D3: 3772.1,3829 3762.71,3830.94 3762.71,3823.07 3772.1,3825
  region net SDC1_D1: 3772.1,3840.75 3772.1,3844.75 3762.71,3846.69 3762.71,3838.82
  region net SDC1_D0: 3772.1,3860.5 3762.71,3862.44 3762.71,3854.57 3772.1,3856.5
  region net SDC1_CMD: 3772.1,3876.25 3762.71,3878.19 3762.71,3870.32 3772.1,3872.25
  region net $3N3723: 3506.46,3854.5 3506.46,3862.5 3494.46,3867.36 3494.46,3845.36
  region net 3V3: 3503.5,3817.13 3503.5,3825.13 3494.46,3833.36 3494.46,3811.36
  region net $3N3727: 3500.32,3791.3 3494.67,3796.96 3474.7,3791.13 3494.49,3771.33
  region net $3N3727: 3487.49,3760.13 3494.49,3769.13 3472.49,3769.13 3479.49,3760.13
  region net DSI_PWM: 4049.34,3130.29 4051.01,3134.28 4046.77,3145.59 4038.02,3134.53
  region net DSI_PWM: 4034.92,3162.53 4029.92,3156.53 4043.92,3156.53 4038.92,3162.53
  region net LEDK: 4077.92,3162.54 4072.92,3156.54 4086.92,3156.54 4081.92,3162.54
  region net LEDA: 3950.5,3279.8 3932.5,3279.8 3924.19,3252.8 3957.65,3252.8
  region net LEDA: 3969.65,3240.06 3957.65,3250.06 3957.65,3222.06 3969.65,3232.06
  region net VBUS: 4021.72,3300.2 4044.12,3318.24 3996.92,3318.24 4003.72,3300.2
  region net $1N26471: 4104.32,3291.24 4118.92,3318.24 4071.72,3318.24 4086.32,3291.24
  region net 3V3: 4364.5,3638.13 4371.35,3647.13 4351.66,3647.13 4358.5,3638.13
  region net 3V3: 4366.51,3678.13 4360.51,3678.13 4353.01,3669.13 4371.35,3669.13
  region net SPI0_CS: 4312.74,3641.82 4326.88,3647.13 4315.66,3660.66 4310.36,3646.52
  region net 3V3: 4380.34,3625.13 4371.34,3632.63 4371.34,3611.63 4380.34,3619.13
  region net 3V3: 4364.5,3642.13 4358.5,3642.13 4351.66,3633.13 4371.34,3633.13
  region net SPI0_WP: 4327.5,3605.13 4332.5,3611.13 4318.5,3611.13 4323.5,3605.13
  region net 3V3: 4239.5,3206.14 4243.5,3206.14 4248.5,3212.14 4234.5,3212.14
  region net 3V3: 4227.41,3234.39 4231.66,3223.08 4240.4,3234.14 4229.08,3238.38
  region net SPI0_HOLD: 4275.5,3240.14 4270.5,3234.14 4284.5,3234.14 4279.5,3240.14
  region net SPI0_WP: 4310.46,3564.92 4310.46,3559.26 4315.2,3556.93 4314.7,3576.23
  region net SPI0_WP: 4327.5,3602.33 4323.5,3602.33 4318.5,3596.33 4332.5,3596.33
  region net SPI0_MISO: 4274.5,3550.93 4278.5,3550.93 4283.5,3556.93 4269.5,3556.93
  region net SPI0_CS: 4235.47,3601.64 4221.33,3596.33 4238.3,3588.56 4242.54,3601.64
  region net SPI0_CS: 4224.5,3556.13 4228.5,3556.13 4233.5,3556.93 4219.5,3556.93
  region net 3V3: 4224.5,3243.93 4228.5,3243.93 4233.5,3249.93 4219.5,3249.93
  region net SPI0_MOSI: 4359.4,3256.07 4359.4,3248.99 4369.17,3249.93 4364.7,3270.21
  region net SPI0_MOSI: 4378.5,3295.33 4374.5,3295.33 4369.5,3289.33 4383.5,3289.33
  region net SPI0_CLK: 4327.5,3295.13 4323.5,3295.13 4318.5,3289.33 4332.5,3289.33
  region net SPI0_HOLD: 4271.5,3295.33 4266.5,3289.33 4280.5,3289.33 4275.5,3295.33
  region net SPI0_HOLD: 4275.5,3243.93 4279.5,3243.93 4284.5,3249.93 4270.5,3249.93
  region net LEDA: 3950.5,3250.23 3956.25,3277.23 3926.75,3277.23 3932.5,3250.23
  region net $1N26471: 4104.32,3309.39 4086.32,3309.39 4082.02,3282.39 4124.22,3282.39
  region net LEDK: 4085.6,3182.44 4091.26,3182.44 4102.57,3186.69 4082.77,3186.69
  region net LEDK: 4064.5,3203.14 4064.5,3191.14 4082.02,3186.69 4082.02,3207.59
  region net DSI_PWM: 4024.58,3182.44 4030.24,3182.44 4033.07,3186.69 4013.27,3186.69
  region net LEDA: 3979.62,3242.13 3979.62,3234.13 3991.62,3224.13 3991.62,3244.99
  region net VBUS: 4021.72,3300.2 4003.72,3300.2 3991.62,3282.39 4033.82,3282.39
  region net SPK-: 4733.44,3162.19 4736.39,3190.95 4729.32,3198.02 4700.56,3195.07
  region net SPK+: 4804.44,3195.07 4776.39,3197.32 4769.32,3190.24 4771.56,3162.19
  region net 3V3: 4366.51,3676.13 4374.01,3685.13 4353.01,3685.13 4360.51,3676.13
  region net 0V9: 4120.5,3625.13 4128,3634.13 4107.49,3634.13 4114.5,3625.13
  region net 0V9: 4100.5,3608.13 4091.5,3615.63 4091.5,3594.63 4100.5,3602.13
  region net 1V8: 4074.5,3479.13 4094.5,3479.13 4094.51,3511.13 4072.51,3511.13
  region net 1V8: 4074.5,3527.13 4072.51,3511.13 4094.51,3511.13 4094.5,3527.13
  region net 1V8: 4423.5,3473.13 4443.5,3473.13 4445.49,3503.13 4423.49,3503.13
  region net 1V8: 4423.5,3555.13 4423.49,3503.13 4445.49,3503.13 4443.5,3555.13
  region net 3V3: 4906.48,3507.58 4901.44,3509.61 4887.3,3504.31 4901.18,3493.44
  region net SDC0_CMD: 4842.22,3510.67 4839.13,3505.27 4845.5,3488.3 4859.19,3504.31
  region net SDC0_D3: 4842.22,3556.36 4839.13,3550.96 4845.5,3533.99 4859.19,3549.99
  region net 3V3: 4888.34,3602.29 4881.5,3595.68 4901.18,3595.68 4894.34,3602.29
  region net SDC0_D2: 4841.35,3602.04 4845.5,3587.29 4865.18,3595.68 4849.83,3602.04
  region net 3V3: 3556.7,3217.93 3564.7,3217.93 3566.2,3219.58 3555.2,3219.58
  region net CTP_EINT: 3537,3207.58 3545,3207.58 3546.5,3219.58 3535.5,3219.58
  region net CTP_SCL: 3525.4,3207.58 3526.9,3219.58 3515.9,3219.58 3517.4,3207.58
  region net CTP_SDA: 3505.7,3207.58 3507.2,3219.58 3496.2,3219.58 3497.7,3207.58
  region net CTP_SDA: 3497.7,3259.33 3496.2,3251.08 3507.2,3251.08 3505.7,3259.33
  region net CTP_RST: 3478,3213.63 3486,3213.63 3487.5,3219.58 3476.5,3219.58
  region net CTP_RST: 3478,3263.08 3476.5,3251.08 3487.5,3251.08 3486,3263.08
  region net CTP_EINT: 3682.66,3186.13 3694.66,3180.14 3694.66,3202.14 3682.66,3194.13
  region net 3V3: 3725.35,3179.53 3727.73,3174.83 3741.87,3180.14 3730.66,3193.67
  region net 3V3: 3743,3209.64 3738,3209.64 3731.75,3202.14 3749.25,3202.14
  region net CTP_SCL: 3682.66,3233.14 3682.66,3225.14 3694.66,3218.14 3694.66,3240.14
  region net 3V3: 3743,3210.64 3749.25,3218.14 3731.75,3218.14 3738,3210.64
  region net 3V3: 3743,3247.64 3738,3247.64 3731.75,3240.14 3749.25,3240.14
  region net CTP_SDA: 3688.5,3264.14 3694.66,3257.14 3694.66,3279.14 3688.5,3272.14
  region net 3V3: 3743,3249.64 3749.25,3257.14 3731.75,3257.14 3738,3249.64
  region net 3V3: 3743,3286.64 3738,3286.64 3731.75,3279.14 3749.25,3279.14
  region net CTP_RST: 3686.17,3299.46 3686.17,3288.15 3707.3,3295.14 3694.66,3317.14
  region net 3V3: 3743,3287.64 3749.25,3295.14 3731.75,3295.14 3738,3287.64
  region net $1N18373: 3840.72,3414.01 3831.37,3412.26 3831.37,3402.26 3840.72,3400.51
  region net $1N18373: 3620.62,3390.5 3629.97,3392.25 3629.97,3402.25 3620.62,3404
  region net $3N3727: 3567.99,3911 3577.53,3913.53 3578.06,3921.53 3568.89,3924.47
  region net HX2: 3625.51,3950.7 3626.88,3937.64 3630.88,3934.44 3636.05,3942.27
  region net HX1: 3605.78,3943.47 3611.13,3935.33 3615.13,3936.55 3618.69,3947.41
  region net $3N3727: 3619.65,3697.6 3617.13,3707.15 3609.13,3707.71 3606.18,3698.54
  region net 3V3: 3667.25,3699.09 3664.5,3708.43 3656.5,3708.43 3653.75,3699.09
  region net $3N3727: 3714.37,3698.21 3711.62,3707.55 3703.62,3707.55 3700.87,3698.21
  region net $3N3721: 3738.06,3708.12 3728.1,3711.37 3725.27,3708.54 3728.52,3698.57
  region net 3V3: 3588.34,3697.99 3585.63,3707.37 3577.63,3707.49 3574.84,3698.18
  region net $1N22582: 3839.25,3714.09 3836.5,3723.43 3828.5,3723.43 3825.75,3714.09
  region net $1N22582: 3940.55,3788.88 3936.5,3786.13 3936.5,3778.13 3940.55,3775.38
  region net SDC1_CLK: 3956.1,3713.8 3961.5,3706.05 3965.5,3708.03 3968.19,3719.8
  region net SDC1_D3: 3937.75,3692.18 3942.5,3682.83 3946.5,3682.83 3951.25,3692.18
  region net SDC1_D1: 3853.55,3688.88 3844.2,3684.13 3844.2,3680.13 3853.55,3675.38
  region net SDC1_CMD: 4074.06,3775.12 4064.1,3778.37 4061.27,3775.54 4064.52,3765.57
  region net USB_ID: 4116.25,3686.09 4112,3695.43 4107,3695.43 4102.75,3686.09
  region net SDC1_D0: 4053.16,3767.73 4042.99,3772.47 4039.47,3770.33 4041.64,3760.7
  region net WL_REG_ON: 3682.99,3678.37 3678.12,3687.51 3674.12,3687.35 3669.5,3677.8
  region net BT_RSTN: 3718.17,3680.53 3710.41,3675.13 3712.4,3671.13 3724.17,3668.44
  region net SDC1_D2: 4113.52,3741.7 4110.27,3731.73 4113.1,3728.9 4123.06,3732.15
  region net $3N3722: 3580.94,3940.15 3589.49,3935.49 3595.15,3941.14 3590.48,3949.7
  region net WL_WAKE_AP: 3643.55,3678.88 3634.2,3674.13 3634.2,3670.13 3643.55,3665.38
  region net $3N3727: 3487.42,3756.34 3487.49,3767.52 3479.49,3772.86 3476.19,3763.83
  region net AP_WAKE_BT: 3648.75,3958.18 3653.5,3949.13 3657.5,3949.13 3662.25,3958.18
  region net BT_WAKE_AP: 3673.31,3960.4 3671.67,3951.13 3676.01,3949.81 3686.23,3956.48
  region net LPCLK: 3758.06,3726.12 3752.31,3725.15 3749.49,3722.32 3748.52,3716.57
  region net LPCLK: 3750.75,3711.18 3755,3701.83 3760,3701.83 3764.25,3711.18
  region net HXOUT: 4215.75,3746.18 4220.5,3741.13 4224.5,3741.13 4229.25,3746.18
  region net HXIN: 4193.45,3743.47 4198.5,3734.63 4202.5,3735.07 4206.87,3744.96
  region net 0V9: 4117.58,3609.13 4099.97,3608.13 4094.61,3602.13 4105.58,3595.71
  region net 0V9: 4126.5,3605.07 4120.5,3617.53 4114.5,3617.53 4108.5,3605.07
  region net UART2_CTS: 4363.06,3816.12 4353.1,3819.37 4350.27,3816.54 4353.52,3806.57
  region net UART2_RTS: 4379.09,3810.34 4373.89,3800.14 4375.84,3796.43 4385.37,3798.39
  region net UART2_TX: 4407.52,3807.7 4404.27,3797.73 4407.1,3794.9 4417.06,3798.15
  region net UART2_RX: 4396.58,3758.76 4386.38,3767.08 4381.27,3766.54 4383.16,3757.34
  region net USB_ID: 3548.48,3933.57 3552.09,3943.18 3548.55,3946.72 3538.94,3943.12
  region net 3V3: 3588.25,3203.11 3575.9,3208.39 3570.25,3202.73 3575.52,3190.38
  region net 3V3: 3665.44,3148.13 3677.9,3154.63 3677.9,3159.63 3665.44,3166.13
  region net SPI0_CLK: 4273.42,3375.5 4283.62,3367.18 4286.91,3369.55 4286.84,3376.93
  region net SPI0_HOLD: 4317.33,3406.5 4307.44,3402.13 4306.99,3398.13 4315.83,3393.09
  region net SPI0_MOSI: 4297.75,3376.18 4301.03,3366.83 4303.09,3374.55 4311.25,3376.18
  region net SPI0_MOSI: 4297.75,3376.18 4297.09,3368.55 4301.03,3366.83 4311.25,3376.18
  region net SPI0_MOSI: 4297.75,3376.18 4302.5,3373.13 4306.5,3373.13 4311.25,3376.18
  region net SPI0_MISO: 4301.25,3463.09 4296.5,3472.43 4292.5,3472.43 4287.75,3463.09
  region net SPI0_CS: 4275.37,3455.46 4278.62,3465.43 4275.79,3468.26 4265.83,3465.01
  region net SPI0_WP: 4323.06,3466.12 4313.1,3469.37 4310.27,3466.54 4313.52,3456.57
  region net 3V3: 4406.06,3619.12 4396.8,3623.07 4392.56,3618.83 4396.52,3609.57
  region net LEDK: 4070.46,3190.39 4079.8,3191.14 4079.8,3203.14 4070.45,3203.89
  region net LEDA: 3983.45,3231.38 3992.8,3234.13 3992.8,3242.13 3983.45,3244.88
  region net LEDA: 3970.15,3243.33 3961.32,3240.06 3963.21,3232.06 3973.26,3230.2
  region net DSI_PWM: 4036.01,3183.39 4026.04,3186.64 4023.22,3183.81 4026.47,3173.84
  region net DSI_PWM: 4029.76,3167.43 4034.92,3158.81 4038.92,3159.48 4043.08,3169.64
  region net DSI_CKP: 4467.17,3706.44 4482.1,3705.13 4489.64,3710.13 4478.42,3713.9
  region net DSI_CKN: 4478.48,3688.57 4478.27,3694.37 4474.73,3697.9 4468.94,3698.12
  region net DSI_CKP: 4389.94,3151.15 4399.55,3147.55 4403.09,3151.08 4399.48,3160.7
  region net DSI_CKN: 4417.28,3153.31 4429.13,3155.13 4432.01,3160.13 4424.03,3165
  region net DSI_D1P: 4411.45,3681.38 4420.8,3685.63 4420.8,3690.63 4411.45,3694.88
  region net DSI_D1N: 4411.45,3653.38 4420.8,3657.63 4420.8,3662.63 4411.45,3666.88
  region net DSI_D0P: 4483.09,3625.94 4492.72,3618.38 4498.58,3619.59 4496.31,3628.66
  region net DSI_D0N: 4463.94,3623.15 4473.55,3619.55 4477.09,3623.08 4473.48,3632.7
  region net DSI_D1N: 4335.94,3185.46 4347.48,3187.63 4349.98,3192.63 4341.98,3197.53
  region net DSI_D1P: 4342.48,3167.57 4345.79,3176.89 4342.25,3180.42 4332.94,3177.12
  region net DSI_D0P: 4427.94,3268.15 4436.73,3265.37 4440.27,3268.9 4437.48,3277.7
  region net DSI_D0N: 4445.75,3270.18 4450,3260.83 4455,3260.83 4459.25,3270.18
  region net 1V8: 4355.25,3409.09 4352.5,3415.15 4344.5,3415.15 4341.75,3409.09
  region net 3V3: 4250.96,3204.22 4242.91,3205.55 4240.08,3202.72 4241.42,3194.67
  region net DSI_PWM: 4419.48,3720.57 4419.91,3727.72 4417.09,3730.55 4409.94,3730.12
  region net DSI_RST: 4345.77,3128.14 4355.27,3125.72 4358.09,3128.55 4354.39,3138.53
  region net DSI_RST: 4501.83,3721.73 4509.59,3727.13 4507.6,3731.13 4495.83,3733.83
  region net 3V3: 4724.45,3566.38 4733.8,3570.13 4733.8,3576.13 4724.45,3579.88
  region net 3V3: 3768.52,3903.7 3763.85,3895.14 3769.51,3889.49 3778.06,3894.15
  region net $1N18373: 3421.8,3316.23 3431.82,3318.13 3433.65,3326.13 3424.8,3329.39
  region net USB_ID: 4054.06,3872.12 4044.45,3875.72 4040.91,3872.18 4044.52,3862.57
  region net VBUS: 4820.34,3471.68 4821.85,3462.2 4831.85,3461.48 4833.8,3470.71
  region net LINEOUTP: 4795.83,3559.18 4786.66,3557.13 4787.78,3547.13 4797.33,3545.76
  region net USB_ID: 4065.17,3793.09 4074.06,3797.63 4073.5,3802.63 4063.67,3806.5
  region net LPCLK: 4207.55,3479.88 4198.2,3475.63 4198.2,3470.63 4207.55,3466.38
  region net SPI0_MOSI: 4216.45,3125.38 4225.8,3129.63 4225.8,3134.63 4216.45,3138.88
  region net 3V3: 3667.25,3699.09 3664.5,3708.43 3656.5,3708.43 3653.75,3699.09
  region net SDC0_D2: 4715.75,3683.18 4719.5,3673.83 4725.5,3673.83 4729.25,3683.18
  region net SDC0_D3: 4722.94,3627.15 4732.2,3623.19 4736.44,3627.44 4732.48,3636.7
  region net SDC0_CMD: 4724.7,3601.21 4736.56,3602.13 4740.56,3608.13 4732.2,3612.44
  region net 3V3: 4870.94,3613.15 4880.2,3609.19 4884.44,3613.44 4880.48,3622.7
  region net CTP_RST: 3371.94,3223.15 3380.49,3218.49 3386.15,3224.14 3381.48,3232.7
  region net CTP_SDA: 3381.36,3176.75 3390.08,3180.13 3387.25,3188.13 3376.86,3189.48
  region net CTP_SCL: 3449.86,3158.78 3460.25,3160.13 3463.08,3168.13 3454.36,3171.51
  region net CTP_EINT: 3531.48,3149.57 3536.15,3158.12 3530.49,3163.78 3521.94,3159.12

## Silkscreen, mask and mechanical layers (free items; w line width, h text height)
Top Overlay:
  text "YuzukiHD x 100ASK" at 4215.15,3841.89 h51.92
  text "1" at 5011.32,3802.13 h39.22 r90
  text "RST" at 3226.18,3752.45 h38.94
  text "Lizard" at 3142.82,3649.59 h38.94 r270
  text "V851S" at 4062.18,3411.39 h38.94 r90
  text "1.1" at 3246.18,3406.45 h38.94
  text "TF Card" at 4553.18,3347.97 h38.94 r90
  text "JLCJLCJLCJLC" at 5121.18,3316.42 h38.94 r90
  text "FEL" at 3233.18,3309.45 h38.94
  text "Camera" at 4977.18,3283.68 h38.94 r90
  text "Display" at 4305.34,3272.45 h38.94
  text "-SPK+" at 4644.76,3221.45 h38.94
  text "24" at 4539.89,3188.45 h38.94
Bottom Overlay:
  text "GND" at 4047.82,3900.46 h38.94 r90
  text "PE11" at 4147.82,3899.92 h38.94 r90
  text "PE12" at 4250.8,3900.49 h38.94 r90
  text "PE10" at 4450.48,3899.92 h38.94 r90
  text "PE14" at 4551.11,3899.92 h38.94 r90
  text "PE13" at 4348.82,3899.17 h38.94 r90
  text "PH13" at 4647.82,3898.92 h38.94 r90
  text "PH12" at 4750.82,3898.07 h38.94 r90
  text "PH11" at 4849.82,3897.17 h38.94 r90
  text "TX0" at 5046.82,3897.46 h38.94 r90
  text "RX0" at 4948.82,3896.36 h38.94 r90
  text "GND" at 5146.82,3896.46 h38.94 r90
  text "5V" at 3946.82,3892.75 h38.94 r90
  text "Yuzukilizard" at 5096.19,3670.55 h71.39
  text "CERN-OHL-S" at 5100.21,3618.45 h38.94
  text "OTG" at 3273.82,3611.46 h38.94 r90
  text "UART" at 3125.18,3472.1 h38.94 r270
  text "GND" at 5145.82,3321.21 h38.94 r90
  text "PH0" at 5046.82,3319.21 h38.94 r90
  text "3V3" at 4947.82,3316.21 h38.94 r90
  text "SP+" at 4847.82,3314.21 h38.94 r90
  text "SP-" at 4747.82,3313.21 h38.94 r90
  text "1" at 3404.5,3188.31 h39.22
  text "CTP" at 3761.18,3117.45 h38.94
Mechanical 1:
  lines w10: 3102.5,3118.13 3102.5,3991.13 3122.5,4011.13 5146.5,4011.13 5166.5,3991.13 5166.5,3118.13 5146.5,3098.13 3122.5,3098.13 3102.5,3118.13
